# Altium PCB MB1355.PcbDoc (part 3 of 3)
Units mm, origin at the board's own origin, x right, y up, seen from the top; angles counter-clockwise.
Board outline 70.13 x 64.58 mm, 4 copper layers (L1, L2, L3, L4), stack 1.565 mm thick; 213 components, 161 nets, 1280 pads, 261 vias.
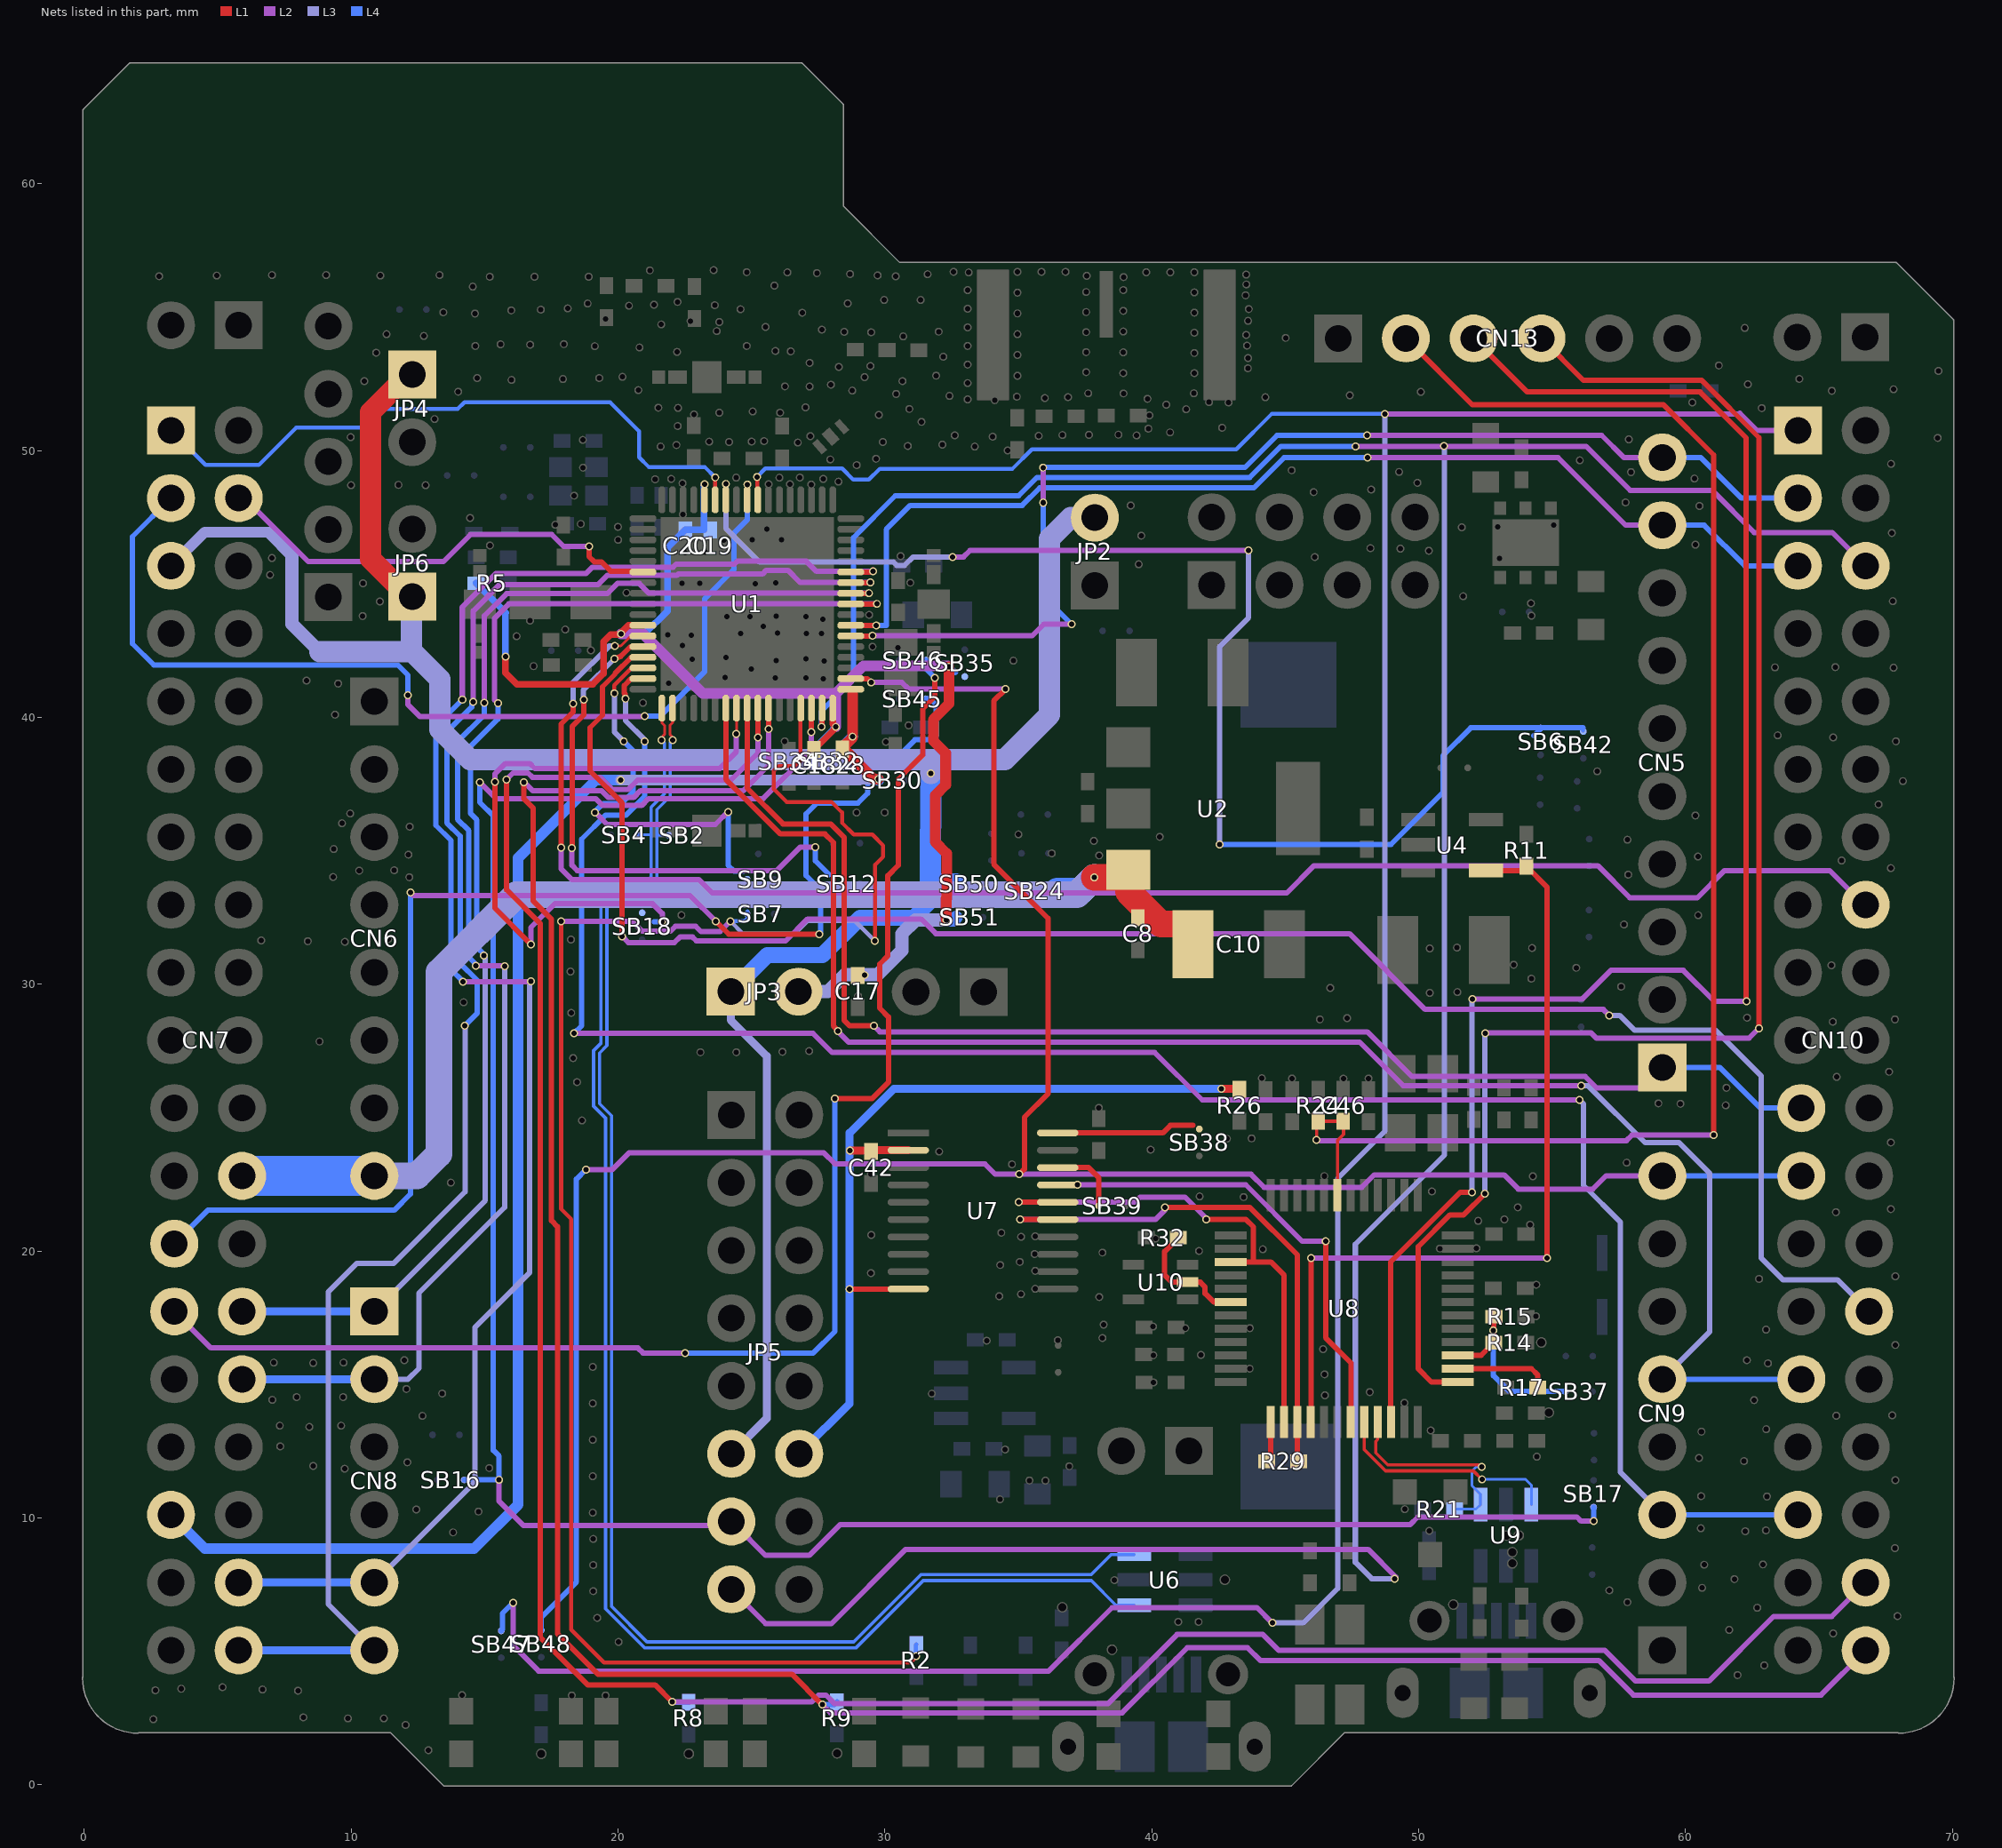
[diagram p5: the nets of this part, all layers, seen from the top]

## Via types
v1: diameter 0.3, hole 0.2, L1 to L4, tented both sides, 254 vias
v2: diameter 0.406, hole 0.203, L1 to L4, tented both sides, 7 vias

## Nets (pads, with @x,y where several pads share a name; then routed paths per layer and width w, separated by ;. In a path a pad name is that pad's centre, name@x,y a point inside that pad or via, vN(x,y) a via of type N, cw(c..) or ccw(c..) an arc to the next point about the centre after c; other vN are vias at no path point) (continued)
PB5: R2.1 SB7.1 U1.65 | length 67.3
  L1 w0.15: v1(17.87,32.352) 17.87,21.583 18.248,21.205 18.248,5.814 19.478,4.584 30.962,4.584 31.168,4.79 v1(31.168,4.829) ; U1.65@26.844,40.349 26.838,40.343 26.838,38.372 26.736,38.269 26.725,38.269 26.625,38.17 26.016,38.17 25.836,37.99 25.836,37.318 26.318,36.836 27.996,36.836 28.392,36.44 28.392,36.053 28.836,35.609 29.529,35.609 29.938,35.2 29.938,34.783 29.63,34.475 v1(29.63,31.634)
  L2 w0.2: v1(17.87,32.352) 20.536,32.352 20.903,31.985 21.963,31.985 22.155,32.177 22.906,32.177 23.108,31.975 23.825,31.975 v1(24.214,32.364)
  L3 w0.15: v1(24.214,32.364) 24.675,31.903 26.636,31.903 27.098,32.365 28.886,32.365 29.63,31.62 v1(29.63,31.634)
  L4 w0.15: v1(17.87,32.352) v1@17.872,32.354 ; v1@24.214,32.384 v1(24.214,32.364) 24.737,32.364 24.847,32.474 SB7.1@24.847,32.739 ; v1(31.168,4.829) 31.168,5.256 R2.1@31.175,5.263
PB6: JP5.13 pad.94 SB16.2 SB17.1 U1.66 | length 86.8
  L1 w0.2: v1(27.244,39.445) U1.66@27.244,40.349
  L2 w0.2: v1(14.816,37.576) 15.436,36.956 19.165,36.956 19.424,36.697 20.885,36.697 21.144,36.956 25.439,36.956 27.244,38.761 v1(27.244,39.445) v1@27.23,39.459 ; pad.94@15.546,11.427 15.546,10.632 16.452,9.726 24.399,9.726 25.529,8.596 27.166,8.596 28.327,9.757 49.69,9.757 49.967,10.034 55.933,10.034 56.089,9.878 v1(56.556,9.878)
  L4 w0.2: SB16.2@14.239,11.429 pad.94@15.544,11.429 15.544,12.321 15.327,12.538 15.327,36.309 14.816,36.82 v1(14.816,37.576) ; v1(56.556,9.878) SB17.1@56.556,10.405
PB7: CN10.6 JP5.15 U1.67 | length 121.5
  L1 w0.2: v1(27.621,39.652) 27.644,39.675 U1.67@27.644,40.349
  L2 w0.2: JP5.15@24.247,7.327 25.535,6.039 27.995,6.039 30.779,8.823 48.109,8.823 49.149,7.783 v1(49.095,7.729) ; v1(47.635,50.159) 56.275,50.159 57.923,48.511 60.99,48.511 62.569,46.932 65.498,46.932 CN10.6@66.75,45.68
  L3 w0.2: v1(49.095,7.729) 48.238,7.729 47.627,8.34 47.627,20.257 50.965,23.595 50.965,50.166 v1(50.955,50.176)
  L4 w0.2: v1(27.621,39.652) 27.621,40.234 28.826,41.439 28.826,46.743 30.389,48.306 35.009,48.306 35.692,48.989 43.667,48.989 44.837,50.159 v1(47.635,50.159)
PB8: CN5.10 CN10.3 pad.100 pad.127 U1.6 | length 44.5
  L1 w0.2: U1.6@28.722,43.052 29.523,43.052 pad.100@29.534,43.063
  L2 w0.2: pad.100@29.534,43.063 35.523,43.063 35.956,43.496 v1(36.992,43.496) ; pad.127@35.925,49.364 35.925,48.095 35.93,48.09 v1(35.93,48.049) ; v1(48.062,50.564) 56.851,50.564 56.857,50.57 57.683,49.744 CN5.10@59.13,49.744
  L4 w0.2: pad.127@35.925,49.368 43.491,49.368 44.693,50.57 44.699,50.564 v1(48.062,50.564) ; v1(35.93,48.049) 35.93,44.558 v1(36.992,43.496) ; CN5.10@59.13,49.744 60.565,49.744 62.089,48.22 CN10.3@64.21,48.22
PB9: CN5.9 CN10.5 pad.101 U1.7 | length 41.7
  L1 w0.2: U1.7@28.722,43.452 29.51,43.452
  L2 w0.2: v1(48.077,49.74) 55.222,49.74 57.758,47.204 CN5.9@59.13,47.204
  L4 w0.2: pad.101@29.678,43.448 30.048,43.448 30.048,47.047 30.949,47.948 35.146,47.948 35.803,48.605 43.825,48.605 44.96,49.74 v1(48.077,49.74) ; CN5.9@59.13,47.204 60.696,47.204 62.22,45.68 CN10.5@64.21,45.68
PB10: pad.72 SB6.2 SB42.1 U1.28 | length 50.3
  L2 w0.2: v1(32.543,46.016) 32.948,46.016 33.184,46.252 v1(43.628,46.252)
  L3 w0.2: pad.72@24.042,48.749 24.042,47.086 25.308,45.82 30.323,45.82 30.447,45.696 30.737,45.696 31.057,46.016 v1(32.543,46.016) ; v1(42.546,35.247) 42.546,42.659 43.628,43.741 v1(43.628,46.252)
  L4 w0.127: SB6.2@54.57,39.602 SB6.2@54.58,39.612 ; SB42.1@56.155,39.496 56.155,39.612
  L4 w0.2: v1(42.546,35.247) 48.968,35.247 50.907,37.186 50.907,38.567 51.95,39.61 54.606,39.61 54.314,39.318 ; SB6.2@54.58,39.612 56.155,39.612
PB11: CN7.1 pad.71 U1.29 | length 24.5
  L1 w0.15: U1.29@23.64,48.159 pad.71@23.64,48.996
  L4 w0.15: CN7.1@3.25,50.76 4.544,49.466 6.548,49.466 7.938,50.856 10.412,50.856 11.117,51.561 13.993,51.561 14.244,51.812 19.702,51.812 20.791,50.723 20.791,49.746 21.15,49.387 23.249,49.387 pad.71@23.64,48.996
PB12: CN10.16 pad.86 U1.46 | length 61.6
  L1 w0.1: pad.86@19.88,42.678 20.106,42.678 20.48,43.052 U1.46@20.941,43.052
  L1 w0.2: v1(17.87,35.119) 17.87,39.757 18.32,40.207 v1(18.32,40.516)
  L2 w0.2: v1@17.877,35.102 17.877,34.316 18.262,33.931 23.025,33.931 23.536,33.42 45.055,33.42 46.077,34.442 56.713,34.442 57.912,33.243 60.441,33.243 61.459,34.261 65.398,34.261 66.679,32.98 CN10.16@66.75,32.98
  L3 w0.2: v1(18.32,40.516) 18.32,41.323 19.675,42.678 pad.86@19.88,42.678
PB13: pad.87 SB12.1 U1.47 | length 21.2
  L1 w0.1: 20.076,42.29 20.032,42.315 20.468,42.682 U1.47@20.468,42.652
  L1 w0.2: v1(18.272,35.109) 18.282,35.119 18.282,39.66 18.721,40.099 v1(18.721,40.659) ; pad.87@19.866,42.196 20.097,42.281 20.468,42.652 U1.47@20.941,42.652
  L2 w0.2: v1(18.272,35.109) 18.272,34.461 18.469,34.264 25.952,34.264 26.821,35.133 v1(27.391,35.133)
  L3 w0.2: v1@18.71,40.542 v1@18.71,40.648 ; v1(18.721,40.659) v1@18.71,40.648 ; pad.87@19.866,42.196 18.71,41.04 v1@18.71,40.648
  L4 w0.2: v1(27.391,35.133) 27.391,34.629 27.912,34.108
PB14: CN10.28 U1.48 | length 69.4
  L1 w0.15: U1.48@20.483,42.252 U1.48@20.941,42.252
  L1 w0.17: 19.418,41.15 19.897,41.629 19.897,41.657
  L1 w0.2: 19.418,41.15 19.418,40.085 18.952,39.619 18.952,37.999 20.154,36.797 v1(20.154,31.796) ; 19.897,41.657 U1.48@20.483,42.242
  L2 w0.2: v1(20.154,31.796) 20.389,31.561 22.112,31.561 22.324,31.773 22.791,31.773 22.938,31.626 26.28,31.626 27.102,32.448 31.358,32.448 31.909,31.897 47.409,31.897 50.247,29.059 56.92,29.059 v1(57.148,28.831)
  L3 w0.2: v1(57.148,28.831) 57.155,28.838 57.53,28.838 58.084,28.284 61.113,28.284 62.827,26.57 62.827,19.746 63.644,18.929 65.688,18.929 CN10.28@66.877,17.74
PB15: pad.89 pad.135 SB9.1 U1.49 | length 15.5
  L1 w0.15: pad.89@19.863,40.906 19.863,41.208 20.507,41.852 U1.49@20.941,41.852
  L2 w0.2: v1@19.141,36.437 v1(19.138,36.44) 19.59,35.988 23.648,35.988 24.151,36.491 24.151,36.484 v1(24.126,36.459)
  L3 w0.2: pad.89@19.863,40.906 19.863,39.453 pad.135@20.21,39.106
  L4 w0.2: v1(19.138,36.44) 19.132,36.446 19.132,36.458 19.447,36.773 20.132,36.773 20.569,37.21 20.569,38.747 pad.135@20.21,39.106 ; v1(24.126,36.459) 24.126,34.456 24.349,34.233 24.72,34.233
PC0: CN7.28 CN8.1 pad.103 U1.9 | length 49
  L1 w0.2: U1.9@28.722,44.252 29.696,44.252 pad.103@29.698,44.254
  L2 w0.2: v1(15.499,40.529) 15.375,40.653 15.375,43.715 15.914,44.254 pad.103@29.698,44.254
  L3 w0.2: CN8.1@10.87,17.74 15.029,21.899 15.029,31.072 15.019,31.082 v1(14.976,31.082)
  L4 w0.2: v1(14.976,31.082) 15.023,31.082 14.714,31.391 14.714,36.161 14.466,36.409 14.466,38.905 15.499,39.938 v1(15.499,40.529)
  L4 w0.3: CN7.28@5.917,17.74 CN8.1@10.87,17.74
PC1: CN7.30 CN8.2 pad.104 U1.10 | length 53.8
  L1 w0.2: U1.10@28.722,44.652 29.398,44.652 pad.104@29.402,44.656
  L2 w0.2: v1(14.679,30.69) 15.738,30.69 v1(15.751,30.677) ; v1(14.991,40.543) 14.991,43.807 15.825,44.641 19.601,44.641 19.98,45.02 20.793,45.02 21.157,44.656 pad.104@29.402,44.656
  L3 w0.2: CN8.2@10.87,15.2 12.134,15.2 12.542,15.608 12.542,18.429 15.751,21.638 v1(15.751,30.677)
  L4 w0.2: v1(14.679,30.69) 14.679,30.744 14.414,31.009 14.414,35.758 13.988,36.184 13.988,39.087 14.991,40.09 v1(14.991,40.543)
  L4 w0.3: CN7.30@5.917,15.2 CN8.2@10.87,15.2
PC2: CN7.38 CN8.6 U1.11 | length 65.3
  L1 w0.2: U1.11@28.722,45.052 29.459,45.052 v1(29.463,45.056)
  L2 w0.2: v1(14.579,40.584) 14.579,43.992 15.571,44.983 19.257,44.983 19.594,45.32 22.206,45.32 22.261,45.375 25.415,45.375 25.555,45.516 26.368,45.516 26.828,45.056 v1(29.463,45.056) v1@29.491,45.028
  L3 w0.2: CN8.6@10.87,5.04 9.139,6.771 9.139,18.467 10.209,19.537 11.589,19.537 14.275,22.223 v1@14.275,28.454
  L4 w0.2: v1(14.263,28.454) 14.73,28.921 14.73,30.144 14.084,30.79 14.084,35.557 13.589,36.052 13.589,39.458 14.516,40.385 14.516,40.549 14.579,40.612 v1(14.579,40.584)
  L4 w0.3: CN7.38@5.79,5.04 CN8.6@10.87,5.04
PC3: CN7.36 CN8.5 U1.12 | length 64.6
  L1 w0.2: U1.12@28.722,45.452 29.481,45.452 29.551,45.522 v1(29.551,45.47)
  L2 w0.2: v1(14.166,40.667) 14.166,44.134 15.421,45.389 18.799,45.389 19.042,45.632 22.065,45.632 22.177,45.744 24.362,45.744 24.471,45.854 27.052,45.854 27.436,45.47 v1(29.551,45.47) ; v1(14.194,30.103) 16.722,30.103 v1(16.733,30.114)
  L3 w0.2: CN8.5@10.87,7.58 14.637,11.347 14.637,17.14 16.681,19.184 16.681,30.062 v1(16.733,30.114)
  L4 w0.2: v1(14.166,40.667) 13.177,39.678 13.177,35.955 13.741,35.391 13.741,30.556 v1(14.194,30.103)
  L4 w0.3: CN7.36@5.79,7.58 CN8.5@10.87,7.58
PC4: CN10.1 pad.75 SB47.2 U1.25 | length 122.1
  L1 w0.15: U1.25@25.21,48.189 25.21,48.557 25.226,48.557 25.226,48.996 pad.75@25.21,49.012
  L2 w0.2: v1(16.075,6.829) 16.075,5.213 17.025,4.263 36.136,4.263 38.511,6.638 43.944,6.638 v1(44.516,6.066) ; v1(48.729,51.363) 61.982,51.363 61.989,51.37 61.995,51.364 62.029,51.398 62.667,50.76 CN10.1@64.21,50.76
  L3 w0.2: v1(44.516,6.066) 45.679,6.066 46.971,7.358 46.971,22.728 48.727,24.484 48.727,51.361 v1(48.729,51.363)
  L4 w0.15: pad.75@25.21,49.012 25.524,49.326 28.395,49.326 28.81,48.911 29.403,48.911 29.813,49.321 34.781,49.321 35.509,50.049 43.168,50.049 44.49,51.371 48.721,51.371 v1(48.729,51.363)
  L4 w0.2: SB47.2@15.625,5.77 15.672,5.817 15.672,6.426 v1(16.075,6.829)
PC5: CN7.3 pad.74 U1.26 | length 37.6
  L2 w0.2: v1(12.131,40.827) 12.131,40.478 12.571,40.038 21.006,40.038 v1(21.006,40.046)
  L4 w0.2: CN7.3@3.25,48.22 1.807,46.777 1.807,42.763 2.607,41.963 11.751,41.963 12.131,41.583 v1(12.131,40.827) ; v1(21.006,40.046) 21.574,40.046 23.24,41.712 23.24,44.443 24.342,45.545 24.342,46.906 24.851,47.415 pad.74@24.851,48.728
PC6: CN9.3 CN10.33 pad.90 U1.50 | length 76.3
  L1 w0.2: pad.90@20.277,40.704 20.265,40.736 20.265,40.882 20.241,40.907 20.241,41.197 20.496,41.452 U1.50@20.941,41.452
  L2 w0.2: v1(18.349,28.159) 27.31,28.159 28.024,27.445 40.112,27.445 41.891,25.666 v1(56.027,25.666)
  L3 w0.2: pad.90@20.277,40.704 20.277,39.883 21.002,39.158 v1(21.002,39.106) ; v1(56.027,25.666) 56.174,25.519 56.174,22.47 57.563,21.081 57.563,11.711 59.13,10.144 CN9.3@59.13,10.12
  L4 w0.2: v1(18.349,28.159) 18.635,28.445 18.635,35.44 19.527,36.332 20.293,36.332 21.002,37.041 v1(21.002,39.106) ; CN9.3@59.13,10.12 CN10.33@64.21,10.12
PC10: CN9.5 CN10.29 U1.58 | length 63.4
  L1 w0.2: U1.58@24.044,40.349 24.044,37.683 26.091,35.636 27.752,35.636 28.067,35.321 28.067,28.44 v1@28.252,28.255
  L2 w0.2: v1(28.248,28.255) 28.248,28.222 28.637,27.833 47.785,27.833 49.42,26.198 v1(56.096,26.196)
  L3 w0.2: v1(56.096,26.196) 56.355,26.196 58.488,24.063 59.762,24.063 60.9,22.925 60.9,16.97 CN9.5@59.13,15.2
  L4 w0.2: CN9.5@59.13,15.2 CN10.29@64.337,15.2
PC11: SB18.2 U1.59 | length 24.9
  L1 w0.1: v1(24.435,39.387) 24.444,39.396 U1.59@24.444,40.349
  L1 w0.2: v1(15.389,37.592) 15.389,32.852 16.733,31.508 v1(16.733,31.489)
  L2 w0.2: v1(15.389,37.592) 15.385,37.596 15.385,37.88 15.779,38.274 16.698,38.274 16.886,38.086 23.805,38.086 24.435,38.716 v1(24.435,39.387) ; v1(16.733,31.489) 16.733,32.124 17.631,33.022 21.292,33.022 21.658,32.656 21.658,32.335 v1(21.653,32.335)
  L4 w0.2: 21.351,32.348 21.364,32.335 v1(21.653,32.335)
PC12: CN5.1 CN10.21 U1.60 | length 52.1
  L1 w0.2: U1.60@24.844,40.349 24.844,37.346 26.183,36.007 27.973,36.007 28.472,35.508 28.472,28.652 28.68,28.444 v1(29.591,28.444)
  L2 w0.2: v1(29.591,28.444) 29.813,28.222 48.075,28.222 49.751,26.546 56.241,26.546 56.674,26.113 58.359,26.113 CN5.1@59.13,26.884
  L4 w0.2: CN5.1@59.13,26.884 61.28,26.884 62.804,25.36 CN10.21@64.337,25.36
PC13: CN9.8 CN10.23 pad.97 SB48.2 U1.2 | length 90.5
  L1 w0.2: U1.2@28.722,41.452 29.34,41.452 pad.97@29.483,41.309 ; v1(34.524,41.063) 34.08,40.619 34.08,34.504 36.109,32.475 36.109,25.894 35.231,25.016 35.231,23.076 v1(35.035,22.88)
  L2 w0.2: v1(18.802,23.058) 19.787,23.058 20.409,23.68 27.715,23.68 28.127,23.268 33.745,23.268 34.133,22.88 v1(35.035,22.88) 43.721,22.88 44.212,22.389 47.865,22.389 48.335,22.859 53.201,22.859 53.733,22.327 56.525,22.327 57.018,22.82 CN9.8@59.13,22.82 ; pad.97@29.483,41.309 30.639,41.309 30.891,41.057 30.897,41.063 v1(34.524,41.063)
  L4 w0.2: SB48.2@17.124,5.793 17.124,6.28 18.442,7.598 18.442,22.698 v1(18.802,23.058) ; CN9.8@59.13,22.82 CN10.23@64.337,22.82
PC14: CN7.25 SB45.2 | length 50
  L1 w0.2: v1(23.664,32.363) 24.145,31.882 v1@27.571,31.882
  L2 w0.2: v1(12.219,33.444) 12.341,33.322 22.705,33.322 v1(23.664,32.363)
  L4 w0.2: CN7.25@3.377,20.28 4.631,21.534 11.614,21.534 12.219,22.139 v1(12.219,33.444) ; v1(27.54,31.882) 27.599,31.941 27.599,33.524 27.041,34.082 27.041,36.385 27.445,36.789 28.985,36.789 29.351,37.155 29.351,38.25 29.593,38.492 30.459,38.492 31.129,39.162 31.767,39.162 31.913,39.308 31.913,40.483 31.698,40.698 SB45.2@31.533,40.698
PC15: CN7.27 SB46.2 | length 53.7
  L1 w0.2: v1(28.123,25.72) 29.528,25.72 30.136,26.328 30.136,28.778 29.806,29.108 29.806,30.761 30.113,31.068 30.113,34.072 30.504,34.463 30.504,37.686 31.413,38.595 31.413,40.088 31.416,40.091 31.416,40.323 31.872,40.779 v1(31.872,41.484)
  L2 w0.2: CN7.27@3.377,17.74 4.744,16.373 20.744,16.373 20.936,16.181 v1(22.516,16.181)
  L4 w0.2: v1(22.516,16.181) 27.315,16.181 28.124,16.99 28.124,25.719 v1(28.123,25.72) ; SB46.2@31.543,42.147 31.543,41.813 v1(31.872,41.484)
PD0: CN10.36 R8.2 U1.61 | length 99.6
  L1 w0.2: v1(15.822,37.667) 15.822,33.544 17.084,32.282 17.084,5.529 18.864,3.749 21.386,3.749 v1(22.033,3.102) ; U1.61@25.244,40.349 25.244,39.257 v1(25.246,39.259)
  L2 w0.2: v1(15.822,37.667) 15.822,37.675 16.073,37.926 16.622,37.926 16.79,37.758 19.326,37.758 19.787,37.297 20.378,37.297 20.732,37.651 24.231,37.651 25.246,38.666 v1(25.246,39.259) ; v1(22.033,3.102) 27.251,3.102 27.507,3.358 27.797,3.358 28.105,3.05 38.365,3.05 40.95,5.635 44.161,5.635 44.75,5.046 56.97,5.046 58.126,3.89 60.876,3.89 63.293,6.307 65.477,6.307 CN10.36@66.75,7.58
  L4 w0.2: v1(22.033,3.102) 22.04,3.095 R8.2@22.646,3.095
PD1: CN10.38 R9.2 U1.62 | length 97.8
  L1 w0.2: v1(16.477,37.576) 16.477,36.947 16.825,36.599 16.825,33.118 17.508,32.435 17.508,21.143 17.733,20.918 17.733,5.664 19.249,4.148 26.512,4.148 v1(27.652,3.008) ; U1.62@25.644,40.349 25.644,39.572 v1(25.645,39.571)
  L2 w0.2: v1(16.477,37.576) 16.797,37.256 19.38,37.256 19.639,36.997 20.589,36.997 20.848,37.256 24.7,37.256 25.645,38.201 v1(25.645,39.571) ; v1(27.652,3.008) 27.964,2.696 38.888,2.696 41.327,5.135 43.59,5.135 44.065,4.66 56.749,4.66 58.043,3.366 65.076,3.366 CN10.38@66.75,5.04
  L4 w0.2: v1(27.652,3.008) 28.108,3.008 R9.2@28.203,3.103
PE4: CN7.4 U1.40 | length 17.4
  L1 w0.2: v1(18.911,46.408) 18.917,46.408 18.917,46.027 19.115,45.829 19.377,45.829 19.722,45.484 20.909,45.484 U1.40@20.941,45.452
  L2 w0.2: CN7.4@5.79,48.22 6.015,48.22 8.392,45.843 13.465,45.843 14.474,46.852 17.52,46.852 17.964,46.408 v1(18.911,46.408)
PWR_ENN: R11.2 U4.4 U8.28 | length 31.6
  L1 w0.2: U8.28@45.96,13.596 45.975,13.611 v1(45.975,19.733) ; U4.4@52.523,34.265 53.877,34.265 R11.2@54.034,34.422 54.818,33.638 54.818,19.749 v1(54.811,19.742)
  L2 w0.2: v1(45.975,19.733) 45.979,19.729 45.992,19.742 v1(54.811,19.742)
PWR_EXT: R14.2 R15.1 SB37.2 U8.39 | length 7.2
  L1 w0.2: U8.39@51.46,16.096 52.341,16.096 R14.2@52.811,16.566 52.811,17.536 R15.1@52.821,17.546
  L4 w0.2: v1(52.802,17.035) 52.802,15.337 53.4,14.739 SB37.2@55.503,14.739
STLK_RST: C46.2 CN13.2 R24.1 U8.7 | length 58.3
  L1 w0.127: v1(46.178,24.166) 46.178,24.805 R24.1@46.24,24.867 C46.2@47.17,24.867 47.19,24.847 47.19,24.377 46.96,24.147 U8.7@46.96,22.096
  L1 w0.2: CN13.2@49.52,54.204 52.012,51.712 59.179,51.712 61.054,49.837 61.054,24.355 v1(61.058,24.351)
  L2 w0.2: v1(46.178,24.166) 46.202,24.142 57.783,24.142 57.992,24.351 v1(61.058,24.351)
STLK_RX: SB39.1 U7.18 | length 2.8
  L1 w0.2: U7.18@36.475,23.131 37.637,23.131 38.01,22.758 SB39.1@38.01,21.696
STLK_SWCLK: CN13.4 U8.37 | length 57.9
  L1 w0.2: U8.37@51.46,15.096 50.48,15.096 49.987,15.589 49.987,20.173 51.175,21.361 51.688,21.361 v1(52.482,22.155) ; CN13.4@54.6,54.204 56.176,52.628 60.611,52.628 62.75,50.489 v1(62.75,28.354)
  L2 w0.2: v1(52.496,28.166) 52.513,28.183 56.456,28.183 56.652,27.987 62.383,27.987 v1(62.75,28.354)
  L3 w0.2: v1(52.482,22.155) 52.482,28.162 52.502,28.162 52.506,28.166 v1(52.496,28.166)
STLK_SWDIO: CN13.3 U8.34 | length 61.5
  L1 w0.2: U8.34@48.96,13.596 48.95,13.606 48.95,19.598 51.556,22.204 v1(52.001,22.204) ; CN13.3@52.06,54.204 54.068,52.196 60.551,52.196 62.275,50.472 v1@62.275,29.351
  L2 w0.2: v1(52.021,29.452) 56.13,29.452 57.202,30.524 59.917,30.524 61.079,29.362 v1(62.28,29.362)
  L3 w0.2: v1(52.001,22.204) 52.001,29.432 v1(52.021,29.452)
STLK_TX: SB38.1 U7.20 | length 5.2
  L1 w0.2: U7.20@36.475,24.431 40.417,24.431 40.7,24.714 41.547,24.714
T_NRST: R32.1 U8.18 U10.2 | length 4.7
  L1 w0.2: R32.1@40.999,20.506 40.48,19.987 40.48,19.106 40.75,18.836 U10.2@41.346,18.836 41.82,18.836 42,18.656 42,18.416 42.32,18.096 U8.18@42.96,18.096
T_SWCLK: U7.16 U8.15 U8.26 | length 19.8
  L1 w0.2: v1(35.017,21.834) 35.146,21.834 v1@35.146,21.841 ; v1@35.149,21.831 U7.16@36.475,21.831 ; v1(42.034,21.196) 43.521,21.196 43.811,20.906 43.811,19.596 ; U8.15@42.96,19.596 44.46,19.596 44.96,19.096 U8.26@44.96,13.596
  L2 w0.2: v1(35.017,21.834) 39.368,21.834 39.562,22.028 41.244,22.028 42.034,21.238 v1(42.034,21.196)
T_SWDIO: R29.1 U7.15 U8.27 | length 20.5
  L1 w0.2: v1(35.062,21.187) 35.068,21.181 U7.15@36.475,21.181 ; v1(40.501,21.645) 43.671,21.645 45.46,19.856 U8.27@45.46,13.596 R29.1@45.46,12.175
  L2 w0.2: v1@35.062,21.195 40.151,21.195 40.501,21.545 v1(40.501,21.645)
  L3 w0.2: v1(35.062,21.187) v1@35.062,21.195
T_SWDIO_IN: R29.2 U8.25 | length 1.5
  L1 w0.2: R29.2@44.311,12.126 44.46,12.275 U8.25@44.46,13.596
T_SWO: pad.55 U7.17 U8.31 | length 18.1
  L1 w0.2: U7.17@36.475,22.481 36.48,22.486 v1(37.214,22.486) ; pad.55@46.514,20.37 46.514,16.758 47.47,15.802 47.47,13.606 U8.31@47.46,13.596
  L2 w0.2: v1(37.214,22.486) 43.522,22.486 45.638,20.37 pad.55@46.514,20.37
T_VDD: C42.2 JP5.12 pad.27 R26.2 U7.2 U7.10 | length 32.5
  L1 w0.2: pad.27@28.68,18.581 U7.10@30.875,18.581
  L1 w0.3: v1(28.686,23.776) 29.432,23.776 C42.2@29.478,23.73 29.529,23.781 U7.2@30.875,23.781 ; v1(42.601,26.088) 43.257,26.088 R26.2@43.28,26.065
  L2 w0.3: v1(28.686,23.776) v1@28.709,23.753
  L4 w0.3: JP5.12@26.859,12.467 28.68,14.288 pad.27@28.68,18.577 28.68,24.427 30.341,26.088 v1(42.601,26.088)
USB_N: SB4.1 U1.52 U6.1 | length 57.8
  L1 w0.1: U1.52@21.644,40.349 21.644,39.799 21.744,39.699 21.744,39.361 21.676,39.293
  L4 w0.1: SB4.1@20.758,35.61 21.194,35.61
  L4 w0.12: v1(21.64,39.144) 21.737,39.047 21.737,37.134 21.237,36.634 21.237,34.035 20.552,33.349 19.682,33.349 19.366,33.034 19.366,27.795 19.087,27.516 19.087,25.435 19.536,24.986 19.536,6.597 20.994,5.138 28.923,5.138 31.438,7.653 37.739,7.653 38.658,6.734 U6.1@39.341,6.734
USB_P: SB2.1 U1.53 U6.3 | length 57.3
  L1 w0.1: v1@22.012,39.293 21.944,39.361 21.944,39.699 22.044,39.799 U1.53@22.044,40.349
  L4 w0.1: 21.478,35.588 SB2.1@21.89,35.588
  L4 w0.12: v1(22.054,39.159) 21.957,39.062 21.957,37.043 21.457,36.543 21.457,33.944 20.643,33.129 19.773,33.129 19.586,32.943 19.586,27.704 19.307,27.425 19.307,25.526 19.756,25.077 19.756,6.688 21.085,5.358 28.832,5.358 31.347,7.873 37.722,7.873 38.483,8.634 U6.3@39.341,8.634
USB_RENUMN: R17.2 U8.38 | length 3.6
  L1 w0.2: U8.38@51.46,15.596 54.228,15.596 54.455,15.369 R17.2@54.455,14.889
USBSTLK_N: pad.16 U8.32 U9.6 | length 8.6
  L1 w0.12: U8.32@47.96,13.596 47.96,12.564 48.756,11.768 52.049,11.768 pad.16@52.372,11.445
  L4 w0.1: pad.16@52.372,11.445 54.01,11.445 54.22,11.235 U9.6@54.22,10.504
USBSTLK_P: pad.17 R21.1 U8.33 U9.4 | length 8.2
  L1 w0.1: pad.17@52.357,11.91 pad.17@52.362,11.915
  L1 w0.12: U8.33@48.46,13.596 48.46,12.936 48.39,12.866 48.39,12.445 48.847,11.988 52.289,11.988 pad.17@52.362,11.915
  L4 w0.1: R21.1@51.439,10.334 52.15,10.334 U9.4@52.32,10.504 52.32,10.885 51.994,11.211 51.994,11.758 52.151,11.915 pad.17@52.362,11.915
VBAT: C28.1 CN7.33 pad.138 SB30.2 SB32.1 U1.1 | length 58.5
  L1 w0.4: 28.795,40.873 28.795,39.251 28.41,38.866 29.596,37.68 v1(29.751,37.68)
  L3 w0.4: CN7.33@2.949,10.12 CN7.33@3.25,10.12 ; v1(20.108,37.647) 29.053,37.647 ; 29.162,37.68 v1(29.751,37.68)
  L4 w0.4: CN7.33@3.25,10.12 4.524,8.846 14.6,8.846 16.253,10.499 16.253,34.734 19.166,37.647 v1(20.108,37.647) ; SB32.1@28.396,38.358 28.396,38.89 pad.138@28.786,39.28 ; v1(29.751,37.68) 29.751,37.641 29.76,37.632 SB30.2@29.776,37.648
VDD: CN7.5 JP2.2 JP3.1 JP4.1 JP5.11 JP6.1 SB50.1 | length 94.4
  L1 w0.8: JP6.1@12.163,44.509 10.73,45.942 10.73,51.435 JP4.1@12.192,52.897
  L3 w0.3: JP3.1@24.222,29.723 24.222,28.656 25.571,27.307 25.571,13.731 JP5.11@24.247,12.407
  L3 w0.4: CN7.5@3.25,45.68 4.52,46.95 6.942,46.95 7.012,46.88
  L3 w0.5: 7.012,46.88 7.784,46.108 7.784,43.503 8.823,42.464
  L3 w0.8: 8.823,42.464 12.242,42.464 ; JP6.1@11.983,44.422 12.255,44.15 12.255,42.492 13.321,41.426 13.321,39.546 14.453,38.414 31.622,38.414 ; v1(31.721,37.898) 31.721,38.315 31.622,38.414 ; JP2.2@38.046,47.307 37.863,47.49 36.964,47.49 36.171,46.697 36.171,40.093 34.492,38.414 31.622,38.414
  L4 w0.6: JP3.1@24.222,29.723 25.589,31.09 27.663,31.09 29.07,32.497 31.087,32.497 31.697,33.107 31.697,33.753 31.697,33.761
  L4 w0.8: 31.697,33.753 31.697,33.761 ; v1(31.721,37.898) 31.697,33.761 ; SB50.1@32.66,33.761 31.697,33.761
VDD_MCU: C17.1 C18.1 C19.1 C20.1 JP3.2 pad.70 pad.116 pad.124 pad.130 pad.131 R5.1 SB32.2 SB34.2 SB35.2 SB51.1 U1.30 U1.45 U1.68 | length 55.2
  L1 w0.25: v1(15.784,42.277) 15.784,41.668 16.208,41.244 19.053,41.244 19.457,41.648 19.457,42.841 19.723,43.107 20.049,43.107 20.394,43.452 U1.45@20.941,43.452 ; C18.1@27.344,38.802 pad.116@28.176,39.634 ; U1.68@28.044,40.349 28.044,39.766 pad.116@28.166,39.644
  L1 w0.4: pad.131@32.326,32.41 32.295,32.441 32.295,33.215 32.313,33.233 32.313,34.903 31.885,35.331 31.885,37.081 32.278,37.474 32.278,38.659 31.813,39.124 31.813,39.922 32.411,40.52 v1(32.411,41.893)
  L2 w0.4: pad.124@20.112,43.131 20.942,43.131 23.174,40.899 28.166,40.899 ; pad.116@28.166,39.644 28.166,40.899 ; v1(32.411,41.893) 32.37,41.934 29.201,41.934 28.166,40.899
  L3 w0.5: JP3.2@26.762,29.723 27.862,29.723 28.497,30.358 29.732,30.358 30.633,31.259 30.633,31.889 31.154,32.41 pad.131@32.301,32.41 pad.131@32.311,32.41
  L4 w0.25: R5.1@14.683,45.028 15.795,43.916 15.784,43.905 v1(15.784,42.277) ; pad.124@20.112,43.131 20.991,43.131 21.853,43.993 21.853,46.36 C20.1@22.521,47.028 23.224,47.028 23.224,48.719 pad.70@23.244,48.739 ; SB34.2@26.892,38.352 27.382,38.352 SB32.2@27.388,38.358 ; 27.45,38.668 27.45,38.928 pad.116@28.166,39.644 ; v1(32.411,41.893) 32.595,41.709 32.626,41.709
  L4 w0.5: pad.131@32.301,32.41 32.571,32.41 SB51.1@32.67,32.509
VIN: C8.1 C10.1 CN6.8 CN7.24 pad.109 SB24.2 U2.3 | length 46.5
  L1 w1: pad.109@37.844,34.004 38.845,34.004 U2.3@39.125,34.284 39.125,33.469 40.34,32.254 C10.1@40.796,32.254
  L3 w1: CN6.8@10.87,22.82 12.468,22.82 13.292,23.644 13.292,30.46 16.186,33.354 37.194,33.354 pad.109@37.844,34.004
  L4 w1: 36.459,33.495 37.335,33.495 pad.109@37.844,34.004
  L4 w1.5: CN7.24@5.917,22.82 CN6.8@10.87,22.82
pads on no net: CN6.1 CN7.9 CN7.11 CN7.17 CN7.21 CN7.22 CN7.23 CN7.26 CN7.35 CN7.37 CN10.2 CN10.10 CN10.18 CN13.5 U3.3 U3.5 U7.7 U7.8 U7.9 U8.4 U8.11 U8.14 U8.16 U8.17 U8.19 U8.22 U8.29 U8.40 U8.41 U8.42 U8.43 U8.45 U8.46 U10.1 X3.2 X3.4

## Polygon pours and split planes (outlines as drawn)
GND on L1 "GND_L01_P018" (solid, remove dead copper, pour order 18): 0.837,56.964 75.407,56.964 75.407,-6.596 -1.993,-6.596 -1.993,-6.276 -1.993,56.94 1.387,56.94
ANT on L1 "L2-No Net" (solid, pour order 14): 19.778,57.015 19.778,58.64 17.303,58.64 17.303,59.365 26.228,59.365 26.228,61.015 17.303,61.015 17.303,61.74 26.253,61.74 26.253,63.415 19.278,63.415 19.278,62.965 23.678,62.965 25.778,62.965 25.778,62.215 16.853,62.215 16.853,62.165 16.853,60.54 16.878,60.54 25.753,60.54 25.753,60.165 25.753,59.79 25.678,59.79 16.853,59.79 16.853,59.765 16.853,58.14 16.878,58.14 19.378,58.14 19.378,56.99 19.778,56.99
GND on L3 "GND_L03_P024" (solid, remove dead copper, pour order 24): -3.36,56.887 71.21,56.887 71.21,-6.673 -6.19,-6.673 -6.19,-6.353 -6.19,56.863 -2.81,56.863
GND on L4 "GND_L04_P026" (solid, remove dead copper, pour order 26): -3.139,56.84 71.431,56.84 71.431,-6.72 -5.969,-6.72 -5.969,-6.4 -5.969,56.816 -2.589,56.816
GND on L2 "GND_L02_P030" (solid, remove dead copper, pour order 30): -3.382,56.949 17.183,56.907 17.183,53.644 21.161,53.644 22.55,48.276 23.269,48.276 23.743,48.75 29.442,48.75 30.559,50.012 39.424,50.012 40.416,51.004 40.389,56.925 71.188,56.949 71.188,-6.611 -6.212,-6.611 -6.212,-6.291 -6.212,56.925 -2.832,56.925

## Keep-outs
Keep-Out Layer:
  lines w0.1: 0,4 0,57 ; 0,56.856 0,62.75 1.726,64.476 26.872,64.476 28.396,62.952 28.396,59.142 30.538,57 30.58,57 67.876,57 70,54.876 70,4 ; 2,2 11.5,2 13.514,-0.014 45.186,-0.014 47.2,2 48.5,2 68,2 ; 3.18,2.102 7.652,2.102 7.652,3.044 3.18,3.044 3.18,2.102
  lines w0.127: 0,4 ccw(c2,4) 2,2 ; 68,2 ccw(c68,4) 70,4

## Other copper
L1:
  text "L1" at 3.39,2.274 h0.51
L2:
  text "L2" at 4.484,2.274 h0.51
L3:
  text "L3" at 5.585,2.296 h0.51
L4:
  text "L4" at 6.653,2.296 h0.51

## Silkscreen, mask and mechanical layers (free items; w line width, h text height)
Top Overlay:
  rectangle: 56.232,52.004 58.289,52.708
  lines w0.1: 0.26,57.01 30.333,57.01
  lines w0.2: 19.857,45.441 20.342,45.441 ; 19.867,47.465 20.352,47.465 ; 19.917,41.445 20.402,41.445 ; 20.17,43.44 20.317,43.44 ; 22.817,5.955 19.006,5.955 19.006,26.577 22.817,26.577 ; 22.842,39.295 22.842,39.78 ; 23.242,48.758 23.242,49.002 ; 24.83,39.281 24.83,39.766 ; 25.232,48.792 25.232,49.012 ; 26.846,39.458 26.846,39.773 ; 27.241,48.792 27.241,49.277 ; 28.217,5.955 29.816,5.955 29.816,14.35 28.323,14.35 ; 28.23,11.015 28.23,10.998 29.745,10.998 ; 29.254,46.663 29.739,46.663 ; 29.259,44.65 29.708,44.65 ; 29.279,42.668 29.746,42.668 ; 29.766,31.111 29.766,35.052 35.1,35.052 35.1,31.111 ; 29.769,32.395 35.082,32.395 ; 37.461,11.112 37.461,8.662 42.795,8.662 42.795,11.112 ; 40.775,48.935 40.775,50.685 ; 51.262,48.935 51.262,50.728 ; 51.262,50.728 51.262,51.741 40.775,51.741 40.775,50.728 51.262,50.728 ; 14.829,35.752 31.829,35.752 31.829,52.752 14.829,52.752 14.829,35.752
  text "GND" at 5.21,56.314 h0.51
  text "GND" at 2.66,56.274 h0.51
  text "GND" at 63.63,55.984 h0.51
  text "GND" at 66.32,55.944 h0.51
  text "STLINK (Reserved)" at 47.662,55.576 h0.75
  text "VDD" at 14.403,52.987 h0.51 r90
  text "Vref" at 58.98,52.094 h0.51
  text "NRST" at 48.81,52.074 h0.51
  text "SWCLK" at 53.71,52.074 h0.51
  text "SWDIO" at 51.18,52.064 h0.51
  text "GND" at 46.36,52.014 h0.51
  text "2" at 68.575,50.693 h0.51
  text "1" at 1.245,50.595 h0.51
  text "1" at 62.265,50.597 h0.51
  text "5V sources" at 40.574,50.569 h0.6
  text "VDDRF" at 14.453,49.134 h0.51 r90
  text "5V / VIN" at 45.447,49.093 h0.51 r90
  text "USB / STL" at 50.545,49.115 h0.51 r90
  text "USB / MCU" at 47.965,49.085 h0.51 r90
  text "5V / EXT" at 42.988,49.059 h0.51 r90
  text "D15" at 57.412,48.959 h1 r90
  text "3" at 1.135,48.102 h0.51
  text "4" at 68.575,48.052 h0.51
  text "3" at 62.239,47.85 h0.51
  text "VDD" at 40.002,47.07 h0.51 r90
  text "D14" at 57.462,45.983 h1 r90
  text "VDDSMPS" at 14.396,45.488 h0.51 r90
  text "6" at 68.575,45.435 h0.51
  text "5" at 1.135,45.41 h0.51
  text "5" at 62.239,45.158 h0.51
  text "3V3" at 40.117,44.086 h0.51 r90
  text "AVDD" at 61.85,42.934 h1 r90
  text "8" at 68.575,42.921 h0.51
  text "7" at 1.135,42.768 h0.51
  text "7" at 62.239,42.516 h0.51
  text "8" at 7.474,42.223 h0.51
  text "VDD" at 14.376,42.21 h0.51 r90
  text "GND" at 54.936,41.569 h1
  text "10" at 68.575,40.406 h0.51
  text "9" at 1.159,40.381 h0.51
  text "10" at 7.503,40.33 h0.51
  text "9" at 62.263,40.129 h0.51
  text "D13" at 55.1,39.034 h1
  text "12" at 68.575,37.866 h0.51
  text "11" at 0.98,37.79 h0.51
  text "12" at 7.56,37.805 h0.51
  text "11" at 62.084,37.538 h0.51
  text "D12" at 55.219,36.95 h1
  text "IOREF" at 13.661,36.729 h1 r90
  text "RF Part" at 18.639,36.166 h1
  text "14" at 7.445,35.31 h0.51
  text "13" at 0.762,35.25 h0.51
  text "14" at 68.575,35.25 h0.51
  text "13" at 61.866,34.998 h0.51
  text "NRST" at 12.586,34.417 h1
  text "D11" at 55.421,33.386 h1
  text "16" at 7.445,32.814 h0.51
  text "15" at 0.762,32.786 h0.51
  text "16" at 68.575,32.71 h0.51
  text "15" at 61.866,32.534 h0.51
  text "Ext Battery" at 29.73,32.382 h0.75
  text "3V3" at 13.554,31.563 h1 r90
  text "+" at 33.398,31.366 h1
  text "D10" at 55.127,31.378 h1
  text "-" at 30.692,31.311 h1
  text "18" at 68.575,30.195 h0.51
  text "18" at 7.416,30.176 h0.51
  text "17" at 0.762,30.145 h0.51
  text "17" at 61.866,29.893 h0.51
  text "5V" at 13.59,29.425 h1 r90
  text "D9" at 55.85,28.862 h1
  text "20" at 68.575,27.909 h0.51
  text "20" at 7.474,27.766 h0.51
  text "19" at 0.786,27.706 h0.51
  text "VDD" at 22.507,27.555 h0.51
  text "VDD_MCU" at 25.035,27.518 h0.51
  text "19" at 61.89,27.454 h0.51
  text "GND" at 12.576,27.108 h1
  text "D8" at 55.876,26.346 h1
  text "22" at 7.52,25.275 h0.51
  text "22" at 68.575,25.268 h0.51
  text "21" at 0.9,25.166 h0.51
  text "21" at 61.74,25.12 h0.51
  text "GND" at 20.597,24.777 h0.75
  text "GND" at 12.524,24.708 h1
  text "24" at 68.575,22.601 h0.51
  text "24" at 7.531,22.574 h0.51
  text "23" at 0.682,22.525 h0.51
  text "23" at 61.522,22.479 h0.51
  text "D7" at 55.87,22.264 h1
  text "NRST" at 20.024,22.2 h0.75
  text "VIN" at 12.576,21.996 h1
  text "25" at 0.682,20.086 h0.51
  text "25" at 61.522,20.04 h0.51
  text "26" at 68.575,19.985 h0.51
  text "26" at 7.531,19.964 h0.51
  text "D6" at 55.9,19.784 h1
  text "SWDIO" at 19.642,19.719 h0.75
  text "27" at 0.682,17.648 h0.51
  text "27" at 61.522,17.602 h0.51
  text "28" at 68.575,17.597 h0.51
  text "28" at 7.56,17.497 h0.51
  text "A0" at 12.682,17.192 h1
  text "D5" at 55.85,17.164 h1
  text "SWCLK" at 19.261,17.081 h0.75
  text "30" at 7.503,15.117 h0.51
  text "30" at 68.575,15.032 h0.51
  text "29" at 0.706,14.93 h0.51
  text "29" at 61.546,14.884 h0.51
  text "A1" at 12.763,14.688 h1
  text "SWO" at 20.342,14.661 h0.75
  text "D4" at 55.894,14.666 h1
  text "MB1355C" at 18.243,12.507 h2.5 r90
  text "32" at 7.531,12.478 h0.51
  text "32" at 68.575,12.466 h0.51
  text "31" at 0.9,12.415 h0.51
  text "31" at 61.74,12.369 h0.51
  text "A2" at 12.743,12.293 h1
  text "D3" at 55.829,12.139 h1
  text "VDD / MCU" at 20.215,11.321 h0.75
  text "T_VDD" at 29.923,10.935 h0.6 r90
  text "TX" at 38.208,10.074 h0.75
  text "RX" at 40.891,10.039 h0.75
  text "34" at 7.531,9.982 h0.51
  text "34" at 68.575,9.926 h0.51
  text "33" at 0.682,9.901 h0.51
  text "33" at 61.522,9.855 h0.51
  text "A3" at 12.682,9.681 h1
  text "D2" at 55.76,9.574 h1
  text "TX" at 21.233,9.413 h0.75
  text "RX" at 29.423,9.22 h0.75 r90
  text "STLINK" at 37.537,8.803 h0.75
  text "36" at 68.575,7.412 h0.51
  text "36" at 7.56,7.372 h0.51
  text "35" at 0.682,7.285 h0.51
  text "35" at 61.522,7.239 h0.51
  text "D1" at 55.916,7.194 h1
  text "A4" at 12.682,7.177 h1
  text "RX" at 21.265,6.836 h0.75
  text "TX" at 29.423,6.688 h0.75 r90
  text "Reset" at 38.643,5.595 h1
  text "38" at 7.488,4.745 h0.51
  text "38" at 68.575,4.745 h0.51
  text "37" at 0.682,4.719 h0.51
  text "A5" at 12.682,4.673 h1
  text "37" at 61.522,4.673 h0.51
  text "D0" at 55.85,4.524 h1
  text "COM" at 44.922,4.058 h0.75 r90
Bottom Overlay:
  rectangle: 57.157,17.252 57.62,18.298
  rectangle: 56.12,17.242 56.588,18.298
  lines w0.1: 16.628,47.683 17.203,45.164 ; 29.8,31.116 29.8,28.612 35.074,28.612 35.074,31.142 29.804,31.142 ; 36.36,35.169 36.718,35.236 36.875,38.083 ; 7.089,42.816 7.424,42.816 10.913,42.816 10.913,55.856 7.424,55.856 7.089,55.856 7.089,42.816
  text "GND" at 3.805,55.824 h0.51
  text "GND" at 6.447,55.824 h0.51
  text "GND" at 64.816,55.468 h0.51
  text "GND" at 67.331,55.316 h0.51
  text "GND" at 10.186,54.222 h0.55 r270
  text "2" at 6.696,51.636 h0.51
  text "AT3" at 10.196,51.611 h0.55 r270
  text "2" at 68.607,50.719 h0.51
  text "1" at 1.595,50.515 h0.51
  text "1" at 62.648,50.388 h0.51
  text "4" at 6.696,49.031 h0.51
  text "AT2" at 10.196,48.968 h0.55 r270
  text "4" at 68.631,48.077 h0.51
  text "3" at 1.713,47.975 h0.51
  text "3" at 62.648,47.848 h0.51
  text "AT1" at 10.204,46.498 h0.55 r270
  text "6" at 6.752,46.425 h0.51
  text "6" at 68.583,45.461 h0.51
  text "5" at 1.713,45.435 h0.51
  text "5" at 62.648,45.308 h0.51
  text "8" at 6.752,44.044 h0.51
  text "AT0" at 10.229,43.782 h0.55 r270
  text "8" at 68.607,42.946 h0.51
  text "7" at 1.713,42.895 h0.51
  text "7" at 62.648,42.768 h0.51
  text "Analog Test Pin (Reserved)" at 5.761,41.803 h0.6 r270
  text "10" at 68.979,40.432 h0.51
  text "9" at 1.713,40.355 h0.51
  text "10" at 7.943,40.279 h0.51
  text "9" at 62.648,40.228 h0.51
  text "12" at 68.979,37.892 h0.51
  text "11" at 1.713,37.815 h0.51
  text "12" at 7.943,37.739 h0.51
  text "11" at 62.648,37.688 h0.51
  text "CR2032" at 48.659,36.164 h0.9 r270
  text "13" at 1.713,35.275 h0.51
  text "14" at 69.003,35.275 h0.51
  text "13" at 62.648,35.148 h0.51
  text "14" at 7.967,35.123 h0.51
  text "15" at 1.713,32.735 h0.51
  text "16" at 68.955,32.735 h0.51
  text "15" at 62.648,32.608 h0.51
  text "16" at 7.919,32.583 h0.51
  text "+" at 35.767,31.841 h1 r180
  text "-" at 30.19,31.808 h1 r180
  text "18" at 68.979,30.221 h0.51
  text "17" at 1.713,30.195 h0.51
  text "18" at 7.943,30.068 h0.51
  text "17" at 62.648,30.068 h0.51
  text "CN4" at 28.28,28.483 h1 r270
  text "20" at 69.059,27.935 h0.51
  text "20" at 8.023,27.782 h0.51
  text "19" at 1.713,27.655 h0.51
  text "19" at 62.648,27.528 h0.51
  text "Ext Battery" at 35.922,26.327 h0.75
  text "22" at 69.059,25.293 h0.51
  text "22" at 8.023,25.141 h0.51
  text "21" at 1.713,25.115 h0.51
  text "21" at 62.648,24.988 h0.51
  text "24" at 69.083,22.626 h0.51
  text "23" at 1.713,22.575 h0.51
  text "24" at 8.047,22.474 h0.51
  text "23" at 62.648,22.448 h0.51
  text "25" at 1.713,20.035 h0.51
  text "26" at 69.035,20.01 h0.51
  text "25" at 62.648,19.908 h0.51
  text "26" at 7.999,19.858 h0.51
  text "28" at 69.059,17.622 h0.51
  text "27" at 1.713,17.495 h0.51
  text "28" at 8.023,17.47 h0.51
  text "27" at 62.648,17.368 h0.51
  text "30" at 69.059,15.057 h0.51
  text "29" at 1.713,14.955 h0.51
  text "30" at 8.023,14.905 h0.51
  text "29" at 62.648,14.828 h0.51
  text "32" at 69.059,12.492 h0.51
  text "31" at 1.713,12.415 h0.51
  text "32" at 8.023,12.339 h0.51
  text "31" at 62.648,12.288 h0.51
  text "34" at 69.083,9.952 h0.51
  text "33" at 1.713,9.875 h0.51
  text "34" at 8.047,9.799 h0.51
  text "33" at 62.648,9.748 h0.51
  text "36" at 69.035,7.437 h0.51
  text "35" at 1.713,7.335 h0.51
  text "36" at 7.999,7.285 h0.51
  text "35" at 62.648,7.208 h0.51
  text "37" at 1.713,4.795 h0.51
  text "38" at 69.059,4.77 h0.51
  text "37" at 62.648,4.668 h0.51
  text "38" at 8.023,4.618 h0.51
  text "ST-LINK" at 47.609,2.936 h1 r270
  text "USB_USER" at 44.75,1.794 h1 r270
Mechanical 1:
  lines w0.1: 0,4 0,57 0,62.75 1.726,64.476 26.872,64.476 28.396,62.952 28.396,59.142 30.538,57 32.714,57 67.876,57 70,54.876 70,4 ; 2,2 11.37,2 11.5,2 13.501,-0.001 45.173,-0.001 47.164,1.989 ; 47.2,2 68,2
  lines w0.127: 0,4 ccw(c2,4) 2,2 ; 68,2 ccw(c68,4) 70,4
Mechanical:
  lines w0.1: -3.203,5.04 66.75,5.04 ; -1.991,0 13.5,0 ; 0,-3.336 0,4 ; 0,62.75 0,73.736 ; 3.25,-8.752 3.25,5.04 ; 5.79,-8.857 5.79,5.04 ; 26.872,64.476 79.068,64.476 ; 28.396,62.952 28.396,68.367 ; 45.2,0 79.374,0 ; 46.98,54.245 46.98,61.319 ; 46.98,63 46.98,54.204 87.224,54.204 ; 49.52,54.204 49.52,63 ; 59.68,54.204 59.68,63.443 ; 64.21,-8.708 64.21,5.04 ; 66.75,-13.228 66.75,5.04 ; 66.75,50.76 66.75,70.457 ; 66.812,50.76 87.177,50.76 ; 66.972,1.992 85.981,1.992 ; 67.876,57 83.142,57 ; 70,-13.324 70,4.566 ; 70,54.876 70,73.145 ; 85.836,5.04 66.75,5.04
  lines w0.254: 0,67.306 0,67.814 ; 0,70.68 0,71.188 ; 0.71,-7.539 3.25,-7.539 ; 1.524,67.052 0,67.56 ; 1.524,68.068 0,67.56 ; 1.524,70.426 0,70.934 ; 1.524,71.442 0,70.934 ; 1.726,-8.047 3.25,-7.539 ; 1.726,-7.031 3.25,-7.539 ; 3.25,-7.793 3.25,-7.285 ; 3.25,-4.742 3.25,-4.234 ; 4.774,-4.996 3.25,-4.488 ; 4.774,-3.98 3.25,-4.488 ; 5.79,-7.793 5.79,-7.285 ; 7.314,-8.047 5.79,-7.539 ; 7.314,-7.031 5.79,-7.539 ; 8.078,67.56 0,67.56 ; 8.33,-7.539 5.79,-7.539 ; 20.318,67.56 28.396,67.56 ; 26.872,67.052 28.396,67.56 ; 26.872,68.068 28.396,67.56 ; 28.396,67.306 28.396,67.814 ; 30.404,-4.485 3.25,-4.488 ; 31.801,70.934 0,70.934 ; 38.2,70.934 70,70.934 ; 39.596,-4.484 66.75,-4.481 ; 44.44,61.573 46.98,61.573 ; 45.456,61.065 46.98,61.573 ; 45.456,62.081 46.98,61.573 ; 46.98,61.319 46.98,61.827 ; 49.52,61.319 49.52,61.827 ; 51.044,61.065 49.52,61.573 ; 51.044,62.081 49.52,61.573 ; 52.06,61.573 49.52,61.573 ; 57.14,61.683 59.68,61.683 ; 58.156,61.175 59.68,61.683 ; 58.156,62.191 59.68,61.683 ; 59.68,61.429 59.68,61.937 ; 61.67,-6.001 64.21,-6.001 ; 62.686,-6.509 64.21,-6.001 ; 62.686,-5.493 64.21,-6.001 ; 64.19,68.649 66.73,68.65 ; 64.21,-6.255 64.21,-5.747 ; 64.224,-12.001 66.764,-12.001 ; 65.206,68.141 66.73,68.65 ; 65.206,69.157 66.73,68.65 ; 65.226,-4.989 66.75,-4.481 ; 65.226,-3.973 66.75,-4.481 ; 65.24,-12.509 66.764,-12.001 ; 65.24,-11.493 66.764,-12.001 ; 66.73,68.396 66.73,68.904 ; 66.75,-6.255 66.75,-5.747 ; 66.75,-4.735 66.75,-4.227 ; 66.75,61.429 66.75,61.937 ; 66.764,-12.255 66.764,-11.747 ; 68.274,-6.509 66.75,-6.001 ; 68.274,-5.493 66.75,-6.001 ; 68.274,61.175 66.75,61.683 ; 68.274,62.191 66.75,61.683 ; 68.476,70.426 70,70.934 ; 68.476,71.442 70,70.934 ; 69.29,-6.001 66.75,-6.001 ; 69.29,61.683 66.75,61.683 ; 70,-12.255 70,-11.747 ; 70,68.396 70,68.904 ; 70,70.68 70,71.188 ; 71.524,-12.509 70,-12.001 ; 71.524,-11.493 70,-12.001 ; 71.524,68.142 70,68.65 ; 71.524,69.158 70,68.65 ; 72.54,-12.001 70,-12.001 ; 72.54,68.65 70,68.65 ; 73.723,1.524 74.231,0 ; 73.723,55.476 74.231,57 ; 73.977,0 74.485,0 ; 73.977,57 74.485,57 ; 74.231,25.301 74.231,0 ; 74.231,31.699 74.231,57 ; 74.739,1.524 74.231,0 ; 74.739,55.476 74.231,57 ; 78.084,1.524 78.592,0 ; 78.084,62.952 78.592,64.476 ; 78.338,0 78.846,0 ; 78.338,64.476 78.846,64.476 ; 78.592,26.118 78.592,0 ; 78.592,38.358 78.592,64.476 ; 79.1,1.524 78.592,0 ; 79.1,62.952 78.592,64.476 ; 81.29,52.68 81.798,54.204 ; 81.29,58.524 81.798,57 ; 81.544,54.204 82.052,54.204 ; 81.544,57 82.052,57 ; 81.798,51.664 81.798,54.204 ; 81.798,59.54 81.798,57 ; 82.306,52.68 81.798,54.204 ; 82.306,58.524 81.798,57 ; 86.049,49.236 86.557,50.76 ; 86.049,55.728 86.557,54.204 ; 86.303,50.76 86.811,50.76 ; 86.303,54.204 86.811,54.204 ; 86.557,48.22 86.557,50.76 ; 86.557,56.744 86.557,54.204 ; 87.065,49.236 86.557,50.76 ; 87.065,55.728 86.557,54.204
  text "70mm" at 32.055,70.02 h1.52
  text "28.396mm" at 8.332,66.646 h1.52
  text "3.27mm" at 64.023,64.993 h1.52 r0.01
  text "7.07mm" at 58.873,58.027 h1.52
  text "2.54mm" at 43.908,57.917 h1.52
  text "2.796mm" at 85.455,50.498 h1.52 r90
  text "3.444mm" at 90.214,47.378 h1.52 r90
  text "64.476mm" at 79.506,26.372 h1.52 r90
  text "57mm" at 75.145,25.555 h1.52 r90
  text "63.5mm" at 30.658,-5.399 h1.52 r0.01
  text "2.54mm" at 61.138,-9.658 h1.52
  text "2.54mm" at 0.178,-11.196 h1.52
  text "3.237mm" at 63.278,-15.658 h1.52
